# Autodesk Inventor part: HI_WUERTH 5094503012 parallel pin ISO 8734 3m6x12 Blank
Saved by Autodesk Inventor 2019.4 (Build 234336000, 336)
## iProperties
Created: 2021-06
Part Number: HI_WUERTH 5094503012 parallel pin ISO 8734 3m6x12 Blank
Material: Generic
Document SubType Name: Modeling
Designer: Administrator
Density: 1 g/cm^3
Appearance: Default
Title: HI_WUERTH 5094503012 parallel pin ISO 8734 3m6x12 Blank
Author: Administrator
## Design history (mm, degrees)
feature "Body1"
body "Solid1"
